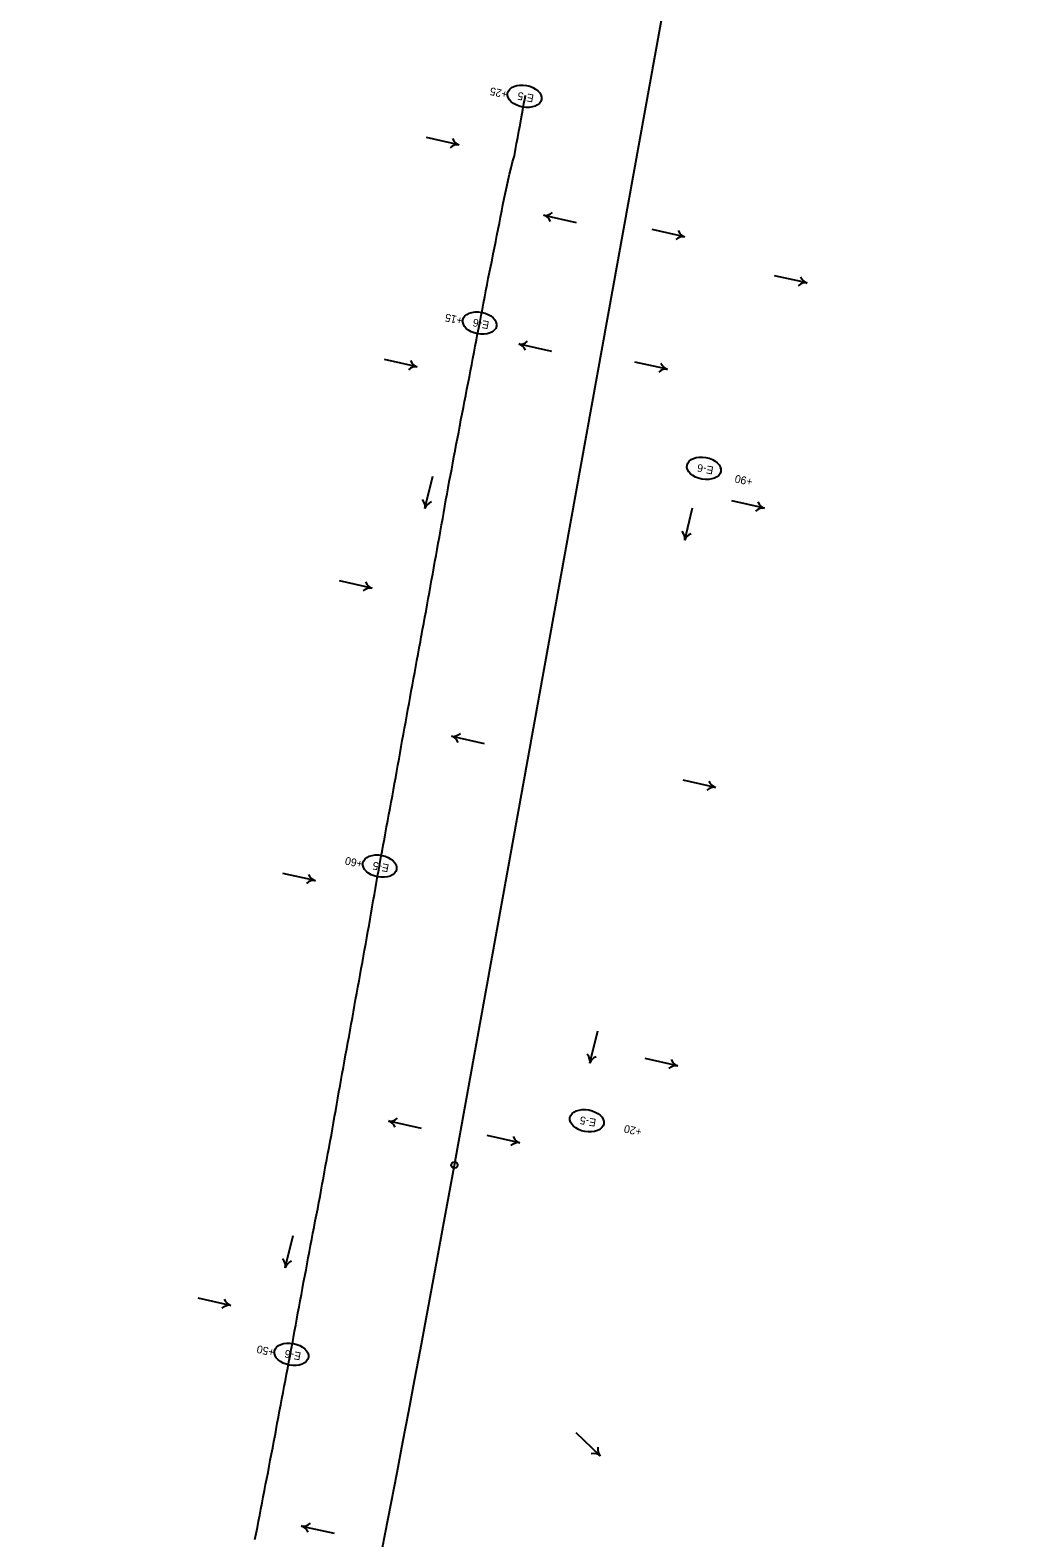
# Model space of a CAD drawing. Extents: x 669236 to 673912, y 735758 to 754788.
# Drawn here: x 670180 to 670963, y 740733 to 741936 of the extents above; entities that cross this region are included whole.
import ezdxf

# ---------------------------------------------------------------- set-up
doc = ezdxf.new("R2010")
doc.units = 0
for name, color, linetype in [('Default', 7, 'Continuous'), ('Prop_Horiz Alignment', 7, 'Continuous'), ('R_Ditchline', 7, 'Continuous'), ('R_Erosion_3', 7, 'Continuous'), ('R_Flow Arrows', 7, 'Continuous')]:
    doc.layers.add(name, color=color, linetype=linetype)

msp = doc.modelspace()

# ---------------------------------------------------------------- linework, layer by layer
at = {"layer": 'Default'}
msp.add_line((670518, 741030.5), (670962.6, 743492), dxfattribs=at)
msp.add_arc((647964.6, 745104.3), 22918.3, 345.76855, 349.76105, dxfattribs=at)
at = {"layer": 'Prop_Horiz Alignment'}
msp.add_circle((670518, 741030.5), 2.5, dxfattribs=at)
at = {"layer": 'R_Ditchline'}
msp.add_lwpolyline([(670358.9, 740731.6), (670359.9, 740736.5), (670360.8, 740741.3), (670361.7, 740746.2), (670362.7, 740751.1), (670363.6, 740756), (670364.6, 740760.9), (670365.5, 740765.8), (670366.5, 740770.7), (670367.4, 740775.6), (670368.3, 740780.5), (670369.3, 740785.3), (670370.2, 740790.2), (670371.1, 740795.1), (670372.1, 740800), (670373.1, 740804.9), (670374, 740809.8), (670374.9, 740814.7), (670375.4, 740817.6), (670375.8, 740819.6), (670376.6, 740824.5), (670377.6, 740829.4), (670378.5, 740834.3), (670379.4, 740839.2), (670380.4, 740844), (670381.3, 740848.9), (670382.2, 740853.8), (670383.2, 740858.7), (670384.1, 740863.6), (670385.1, 740868.5), (670386, 740873.4), (670386.9, 740878.3), (670387.8, 740883.2), (670388.7, 740888.1), (670389.6, 740893), (670390.5, 740897.9), (670391.4, 740902.7), (670392.3, 740907.6), (670393.2, 740912.5), (670394.1, 740917.4), (670395, 740922.3), (670395.9, 740927.2), (670396.8, 740932.1), (670397.7, 740937), (670398.7, 740941.9), (670399.6, 740946.8), (670400.5, 740951.7), (670401.4, 740956.6), (670402.4, 740961.5), (670403.3, 740966.4), (670404.2, 740971.3), (670405.1, 740976.1), (670406.1, 740981), (670407, 740985.9), (670408, 740990.8), (670409, 740995.7), (670409.9, 741000.6), (670410.8, 741005.5), (670411.7, 741010.4), (670412.6, 741015.3), (670413.5, 741020.2), (670414.4, 741025.1), (670415.2, 741030), (670416.2, 741034.9), (670417.1, 741039.7), (670418, 741044.6), (670418.9, 741049.5), (670419.8, 741054.5), (670420.7, 741059.4), (670421.5, 741064.3), (670422.4, 741069.2), (670423.3, 741074.1), (670424.2, 741079.1), (670425, 741084), (670425.9, 741088.9), (670426.8, 741093.8), (670427.7, 741098.8), (670428.5, 741103.7), (670429.4, 741108.6), (670430.3, 741113.5), (670431.2, 741118.4), (670432.1, 741123.4), (670433, 741128.3), (670433.9, 741133.2), (670434.8, 741138.1), (670435.7, 741143), (670436.6, 741148), (670437.4, 741152.9), (670438.3, 741157.8), (670439.2, 741162.7), (670440.1, 741167.7), (670441, 741172.6), (670441.9, 741177.5), (670442.8, 741182.4), (670443.7, 741187.3), (670444.6, 741192.2), (670445.4, 741197.2), (670446.3, 741202.1), (670447.2, 741207), (670448.1, 741211.9), (670449, 741216.8), (670449.9, 741221.8), (670450.7, 741226.7), (670451.5, 741231.6), (670452.4, 741236.6), (670453.2, 741241.5), (670454.1, 741246.4), (670455, 741251.3), (670455.8, 741256.3), (670456.7, 741261.2), (670457.6, 741266.1), (670458.5, 741271), (670459.4, 741275.9), (670460.3, 741280.9), (670461.2, 741285.8), (670462.1, 741290.7), (670463, 741295.6), (670463.9, 741300.5), (670464.8, 741305.5), (670465.7, 741310.4), (670466.6, 741315.3), (670467.6, 741320.2), (670468.5, 741325.1), (670469.4, 741330), (670470.3, 741335), (670471.2, 741339.9), (670472, 741344.8), (670472.9, 741349.7), (670473.8, 741354.6), (670474.7, 741359.6), (670475.6, 741364.5), (670476.4, 741369.4), (670477.3, 741374.3), (670478.2, 741379.2), (670479.1, 741384.2), (670480, 741389.1), (670480.9, 741394), (670481.8, 741398.9), (670482.7, 741403.8), (670483.6, 741408.8), (670484.5, 741413.7), (670485.4, 741418.6), (670486.3, 741423.5), (670487.2, 741428.4), (670488.1, 741433.3), (670489, 741438.3), (670489.9, 741443.2), (670490.8, 741448.1), (670491.5, 741452), (670491.7, 741453), (670492.6, 741457.9), (670493.6, 741462.8), (670494.5, 741467.8), (670495.4, 741472.7), (670496.3, 741477.6), (670497.1, 741482.5), (670498, 741487.5), (670498.9, 741492.4), (670499.8, 741497.3), (670500.7, 741502.2), (670501.6, 741507.1), (670502.4, 741512.1), (670503.3, 741517), (670504.2, 741521.9), (670505.1, 741526.8), (670506, 741531.7), (670506.9, 741536.7), (670507.8, 741541.6), (670508.6, 741546.5), (670509.5, 741551.4), (670510.4, 741556.3), (670511.2, 741561.3), (670512.1, 741566.2), (670513, 741571.1), (670513.9, 741576), (670514.8, 741580.9), (670515.8, 741585.9), (670516.7, 741590.8), (670517.6, 741595.7), (670518.5, 741600.6), (670519.5, 741605.5), (670520.4, 741610.4), (670521.4, 741615.3), (670522.3, 741620.2), (670522.5, 741621.5), (670523.2, 741625.2), (670524.2, 741630.1), (670525.1, 741635), (670526.1, 741639.9), (670527.1, 741644.8), (670528, 741649.7), (670529, 741654.6), (670529.9, 741659.5), (670530.8, 741664.4), (670531.8, 741669.3), (670532.7, 741674.3), (670533.6, 741679.2), (670534.6, 741684.1), (670535.6, 741689), (670536.5, 741693.9), (670537.5, 741698.8), (670538.5, 741703.7), (670539.4, 741708.6), (670540.3, 741713.5), (670541.2, 741718.4), (670542.2, 741723.4), (670543.1, 741728.3), (670544.1, 741733.2), (670545, 741738.1), (670546, 741743), (670547, 741747.9), (670548, 741752.8), (670549, 741757.7), (670549.9, 741762.6), (670550.9, 741767.5), (670551.9, 741772.4), (670552.8, 741777.3), (670553.8, 741782.2), (670554.8, 741787.1), (670555.8, 741792), (670556.7, 741796.9), (670557.7, 741801.8), (670558.7, 741806.7), (670559.7, 741811.6), (670560.9, 741816.5), (670562, 741821.4), (670563.2, 741826.3), (670564.4, 741831.1), (670565.8, 741835.9), (670566.7, 741840.9), (670567.6, 741845.8), (670568.5, 741850.7), (670569.4, 741855.6), (670570.3, 741860.5), (670571.2, 741865.5), (670572.5, 741872.8), (670573.4, 741877.8), (670574.3, 741882.2), (670574.7, 741884.1)], dxfattribs=at)
at = {"layer": 'R_Erosion_3'}
for centre, major_axis in [((670573.9, 741883.5), (-13.5, 2.5)), ((670538.1, 741702.5), (-13.4, 2.6)), ((670717, 741586.6), (-13.5, 2.5)), ((670458.4, 741269.1), (-13.4, 2.6)), ((670623.6, 741065.9), (-13.5, 2.5)), ((670388, 740879.5), (-13.5, 2.5))]:
    msp.add_ellipse(centre, major_axis=major_axis, ratio=0.638788, dxfattribs=at)
at = {"layer": 'R_Flow Arrows'}
for p, q in [((670521.5, 741844.8), (670495.6, 741850.5)), ((670589.3, 741788.6), (670615.2, 741782.8)), ((670701.6, 741771.3), (670675.6, 741777.1)), ((670799.2, 741734.5), (670773.2, 741740.3)), ((670569.4, 741685.8), (670595.3, 741680)), ((670488.2, 741667.5), (670462.3, 741673.3)), ((670687.9, 741665.6), (670662, 741671.4)), ((670494.5, 741554.6), (670500.8, 741580.4)), ((670765.2, 741554.8), (670739.3, 741560.5)), ((670701.7, 741529.3), (670708, 741555.1)), ((670452.2, 741490.9), (670426.3, 741496.7)), ((670515.8, 741372.7), (670541.7, 741367)), ((670726.2, 741331.9), (670700.3, 741337.7)), ((670406.9, 741257.6), (670381, 741263.3)), ((670626.1, 741111.9), (670632.3, 741137.7)), ((670696, 741109.7), (670670.1, 741115.5)), ((670465.5, 741065.7), (670491.4, 741059.9)), ((670570.1, 741048.3), (670544.1, 741054.1)), ((670383, 740948.6), (670389.3, 740974.4)), ((670339.5, 740918.5), (670313.6, 740924.3)), ((670634.2, 740798.5), (670615, 740816.8)), ((670396.1, 740742.4), (670422, 740736.7))]:
    msp.add_line(p, q, dxfattribs=at)
for centre, major_axis, start_param, end_param in [((670517.4, 741825), (4.4, 19.7), 0.023252, 0.620249), ((670526.4, 741864.3), (-4.4, -19.7), 5.662936, 6.259934), ((670584.5, 741769), (4.4, 19.7), 5.662936, 6.259934), ((670593.4, 741808.3), (-4.4, -19.7), 0.023252, 0.620249), ((670706.4, 741790.9), (-4.4, -19.7), 5.662936, 6.259934), ((670697.4, 741751.6), (4.4, 19.7), 0.023252, 0.620249), ((670804, 741754.1), (-4.4, -19.7), 5.662936, 6.259934), ((670795, 741714.8), (4.4, 19.7), 0.023252, 0.620249), ((670573.5, 741705.5), (-4.4, -19.7), 0.023252, 0.620249), ((670564.6, 741666.2), (4.4, 19.7), 5.662936, 6.259934), ((670484.1, 741647.7), (4.4, 19.7), 0.023252, 0.620249), ((670493, 741687.1), (-4.4, -19.7), 5.662936, 6.259934), ((670683.8, 741645.9), (4.4, 19.7), 0.023252, 0.620249), ((670692.7, 741685.2), (-4.4, -19.7), 5.662936, 6.259934), ((670474.9, 741559.1), (19.6, -4.8), 0.023252, 0.620249), ((670514, 741549.4), (-19.6, 4.8), 5.662936, 6.259934), ((670770, 741574.4), (-4.4, -19.7), 5.662936, 6.259934), ((670761.1, 741535), (4.4, 19.7), 0.023252, 0.620249), ((670682.1, 741533.8), (19.6, -4.8), 0.023252, 0.620249), ((670721.2, 741524.1), (-19.6, 4.8), 5.662936, 6.259934), ((670457, 741510.5), (-4.4, -19.7), 5.662936, 6.259934), ((670448.1, 741471.2), (4.4, 19.7), 0.023252, 0.620249), ((670519.9, 741392.5), (-4.4, -19.7), 0.023252, 0.620249), ((670511, 741353.2), (4.4, 19.7), 5.662936, 6.259934), ((670722.1, 741312.2), (4.4, 19.7), 0.023252, 0.620249), ((670731, 741351.5), (-4.4, -19.7), 5.662936, 6.259934), ((670402.8, 741237.8), (4.4, 19.7), 0.023252, 0.620249), ((670411.7, 741277.1), (-4.4, -19.7), 5.662936, 6.259934), ((670606.4, 741116.4), (19.6, -4.8), 0.023252, 0.620249), ((670645.5, 741106.7), (-19.6, 4.8), 5.662936, 6.259934), ((670700.8, 741129.3), (-4.4, -19.7), 5.662936, 6.259934), ((670691.9, 741090), (4.4, 19.7), 0.023252, 0.620249), ((670460.7, 741046.1), (4.4, 19.7), 5.662936, 6.259934), ((670469.6, 741085.4), (-4.4, -19.7), 0.023252, 0.620249), ((670574.9, 741067.9), (-4.4, -19.7), 5.662936, 6.259934), ((670565.9, 741028.6), (4.4, 19.7), 0.023252, 0.620249), ((670363.4, 740953.1), (19.6, -4.8), 0.023252, 0.620249), ((670402.5, 740943.4), (-19.6, 4.8), 5.662936, 6.259934), ((670335.4, 740898.8), (4.4, 19.7), 0.023252, 0.620249), ((670344.3, 740938.1), (-4.4, -19.7), 5.662936, 6.259934), ((670620.5, 740783.7), (13.9, 14.6), 0.023252, 0.620249), ((670648.5, 740812.8), (-13.9, -14.6), 5.662936, 6.259934), ((670391.2, 740722.9), (4.4, 19.7), 5.662936, 6.259934), ((670400.2, 740762.2), (-4.4, -19.7), 0.023252, 0.620249)]:
    msp.add_ellipse(centre, major_axis=major_axis, ratio=0.5625, start_param=start_param, end_param=end_param, dxfattribs=at)

# ---------------------------------------------------------------- texts
at = {"layer": 'R_Erosion_3'}
for s, rotation, p in [('+25', 167.5318, (670560.9, 741887.7)), ('E-5', 169.6427, (670581.7, 741884.7)), ('+15', 166.9809, (670525.1, 741707)), ('E-6', 169.0918, (670546.1, 741703.7)), ('E-6', 169.6427, (670725, 741587.8)), ('+90', 167.5318, (670756.3, 741578.5)), ('+60', 166.9809, (670445.4, 741273.5)), ('E-5', 169.0918, (670466.2, 741270.3)), ('E-5', 169.6427, (670631.4, 741067.2)), ('+20', 167.5318, (670667.9, 741059.7)), ('+50', 167.5318, (670375, 740883.8)), ('E-6', 169.6427, (670396, 740880.8))]:
    msp.add_text(s, height=6.25, rotation=rotation, dxfattribs=at).set_placement(p)

doc.saveas('drawing.dxf')
